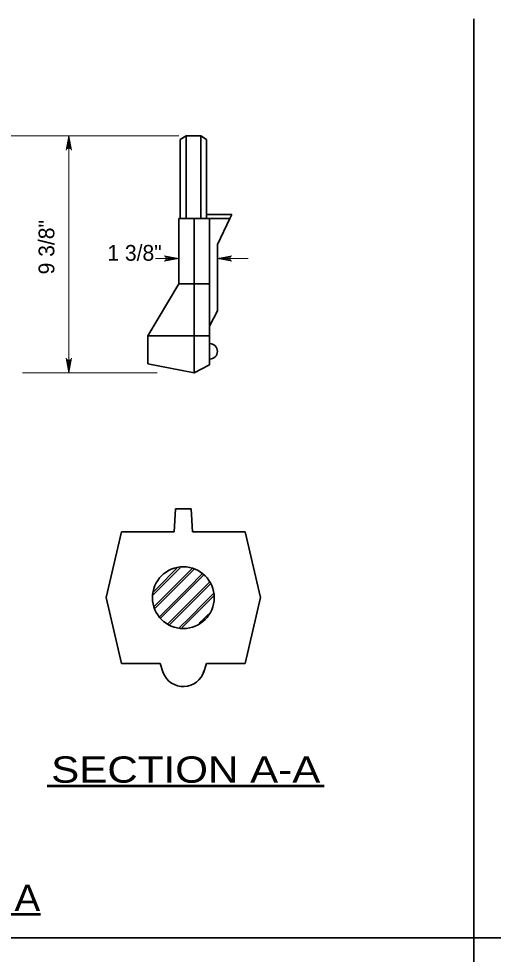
# Model space of a CAD drawing. Extents: x 15 to 140, y -57 to 117.
# Drawn here: x 47.8 to 78.5, y 56.9 to 117.4 of the extents above; entities that cross this region are included whole.
import ezdxf
from ezdxf.enums import TextEntityAlignment as Align

# ---------------------------------------------------------------- set-up
doc = ezdxf.new("R2010")
doc.units = 0
doc.header["$LTSCALE"] = 0.41
for name, color, linetype, lineweight in [('1', 7, 'Continuous', 35), ('10', 7, 'Continuous', 13), ('12', 7, 'Continuous', 53), ('13', 7, 'Continuous', 53), ('6', 7, 'Continuous', 13)]:
    doc.layers.add(name, color=color, linetype=linetype, lineweight=lineweight)

msp = doc.modelspace()

# ---------------------------------------------------------------- linework, layer by layer
at = {"layer": '1'}
for p, q in [((77.2522, 32.9068), (77.2522, 117.3839)), ((58.239, 104.464), (58.239, 109.5703)), ((58.614, 109.8203), (59.564, 109.8203)), ((59.564, 104.464), (59.564, 109.8203)), ((59.564, 109.8203), (59.939, 109.5703)), ((59.939, 104.464), (59.939, 109.5703)), ((58.139, 100.2453), (58.139, 104.464)), ((58.139, 104.464), (61.4495, 104.464)), ((59.139, 94.4953), (59.139, 104.464)), ((60.139, 94.9953), (60.139, 104.464)), ((60.639, 98.4953), (60.639, 102.7756)), ((56.139, 96.8821), (58.139, 100.2453)), ((58.139, 100.2453), (60.139, 100.2453)), ((60.139, 97.4953), (60.639, 98.4953)), ((56.1342, 96.8821), (60.1342, 96.8821)), ((56.139, 95.0784), (56.139, 96.8821)), ((59.139, 94.4953), (56.139, 95.0784)), ((59.139, 94.4953), (60.139, 94.9953)), ((57.9352, 85.6998), (57.8352, 84.1998)), ((57.9352, 85.6998), (58.9352, 85.6998)), ((58.9352, 85.6998), (59.0352, 84.1998)), ((54.4352, 84.1998), (57.8352, 84.1998)), ((59.0352, 84.1998), (62.4352, 84.1998)), ((54.4352, 75.6998), (56.9352, 75.6998)), ((56.9352, 75.6998), (57.1365, 75.0958)), ((59.9352, 75.6998), (59.7341, 75.0967)), ((59.9352, 75.6998), (62.4352, 75.6998)), ((140.4342, 57.946), (15.0728, 57.946))]:
    msp.add_line(p, q, dxfattribs=at)
for points in [[(58.614, 104.464), (58.614, 109.8203), (58.239, 109.5703)], [(59.9439, 104.714), (61.5695, 104.714), (61.4495, 104.464), (60.639, 102.7756)], [(54.4352, 84.1998), (53.4352, 79.9498), (54.4352, 75.6998)], [(62.4352, 84.1998), (63.4352, 79.9498), (62.4352, 75.6998)]]:
    msp.add_lwpolyline(points, dxfattribs=at)
msp.add_circle((58.4352, 79.9498), 2, dxfattribs=at)
for centre, radius, start, end in [((60.139, 95.874), 0.5, 270, 90), ((58.4351, 75.5889), 1.3891, 200.79114, 343.88139)]:
    msp.add_arc(centre, radius, start, end, dxfattribs=at)
at = {"layer": '10'}
for p, q in [((46.3365, 109.8203), (58.1484, 109.8203)), ((51.0273, 94.4953), (51.0273, 109.8203)), ((56.639, 101.8802), (58.139, 101.8802)), ((60.639, 101.8802), (62.639, 101.8802)), ((48.0273, 94.4953), (56.7501, 94.4953))]:
    msp.add_line(p, q, dxfattribs=at)
for points in [[(51.0273, 109.8203), (51.2021, 108.8882), (51.1523, 108.96), (51.0898, 108.9971), (51.0273, 109.0078), (50.9648, 108.9971), (50.9023, 108.96), (50.8525, 108.8882), (51.0273, 109.8203), (50.9023, 108.96), (50.9648, 108.9971), (51.0273, 109.8203), (51.0273, 109.0078), (51.0898, 108.9971), (51.0273, 109.8203), (51.1523, 108.96)], [(58.139, 101.8802), (57.2069, 101.7055), (57.2788, 101.7552), (57.3158, 101.8177), (57.3265, 101.8802), (57.3158, 101.9427), (57.2788, 102.0052), (57.2069, 102.055), (58.139, 101.8802), (57.2788, 102.0052), (57.3158, 101.9427), (58.139, 101.8802), (57.3265, 101.8802), (57.3158, 101.8177), (58.139, 101.8802), (57.2788, 101.7552)], [(60.639, 101.8802), (61.5711, 102.055), (61.4993, 102.0052), (61.4622, 101.9427), (61.4515, 101.8802), (61.4622, 101.8177), (61.4993, 101.7552), (61.5711, 101.7055), (60.639, 101.8802), (61.4993, 101.7552), (61.4622, 101.8177), (60.639, 101.8802), (61.4515, 101.8802), (61.4622, 101.9427), (60.639, 101.8802), (61.4993, 102.0052)], [(51.0273, 94.4953), (50.8525, 95.4274), (50.9023, 95.3555), (50.9648, 95.3185), (51.0273, 95.3078), (51.0898, 95.3185), (51.1523, 95.3555), (51.2021, 95.4274), (51.0273, 94.4953), (51.1523, 95.3555), (51.0898, 95.3185), (51.0273, 94.4953), (51.0273, 95.3078), (50.9648, 95.3185), (51.0273, 94.4953), (50.9023, 95.3555)]]:
    msp.add_lwpolyline(points, dxfattribs=at)
at = {"layer": '12'}
for p, q in [((49.6313, 67.7727), (67.5545, 67.7727)), ((40.2691, 59.4762), (49.1839, 59.4762))]:
    msp.add_line(p, q, dxfattribs=at)
at = {"layer": '6'}
for p, q in [((56.7871, 80.6108), (58.0264, 81.8502)), ((56.9537, 80.6108), (58.2225, 81.8795)), ((57.7871, 80.6108), (58.9884, 81.8121)), ((57.9537, 80.6108), (59.1112, 81.7683)), ((58.7871, 80.6108), (59.6615, 81.4852)), ((58.9537, 80.6108), (59.7408, 81.3978)), ((56.4746, 80.2983), (56.7871, 80.6108)), ((56.4828, 80.1398), (56.9537, 80.6108)), ((56.5294, 79.3531), (57.7871, 80.6108)), ((56.5921, 79.2492), (57.9537, 80.6108)), ((56.9058, 78.7295), (58.7871, 80.6108)), ((56.9685, 78.6256), (58.9537, 80.6108)), ((57.7871, 78.6108), (59.7871, 80.6108)), ((57.9537, 78.6108), (59.8704, 80.5275)), ((59.7871, 80.6108), (59.8704, 80.6941)), ((59.9574, 80.6108), (59.8704, 80.5238)), ((59.8741, 80.6941), (60.139, 80.959)), ((59.9574, 80.6108), (60.2069, 80.8603)), ((59.8741, 79.6941), (60.3739, 80.194)), ((60.4074, 80.0607), (59.8741, 79.5275)), ((58.7871, 78.6108), (59.8704, 79.6941)), ((58.9537, 78.6108), (59.8704, 79.5275)), ((59.7871, 78.6108), (59.8704, 78.6941)), ((59.8741, 78.6941), (60.0467, 78.8667)), ((57.453, 78.2768), (57.7871, 78.6108)), ((57.5576, 78.2146), (57.9537, 78.6108)), ((58.195, 78.0187), (58.7871, 78.6108)), ((58.3544, 78.0115), (58.9537, 78.6108)), ((59.4711, 78.2948), (59.7871, 78.6108))]:
    msp.add_line(p, q, dxfattribs=at)

# ---------------------------------------------------------------- texts
at = {"layer": '12'}
for s, width, p in [('SECTION A-A', 1.2, (58.5929, 67.9852)), ('TYPE A', 1.1, (44.7265, 59.6887))]:
    msp.add_text(s, height=1.7, dxfattribs=dict(at, width=width)).set_placement(p, align=Align.CENTER)
at = {"layer": '13'}
msp.add_text('9 3/8"', height=1.02, rotation=90, dxfattribs=at).set_placement((50.0847, 102.6094), align=Align.CENTER)
msp.add_text('1 3/8"', height=1.02, dxfattribs=at).set_placement((55.2763, 101.7332), align=Align.CENTER)

doc.saveas('drawing.dxf')
